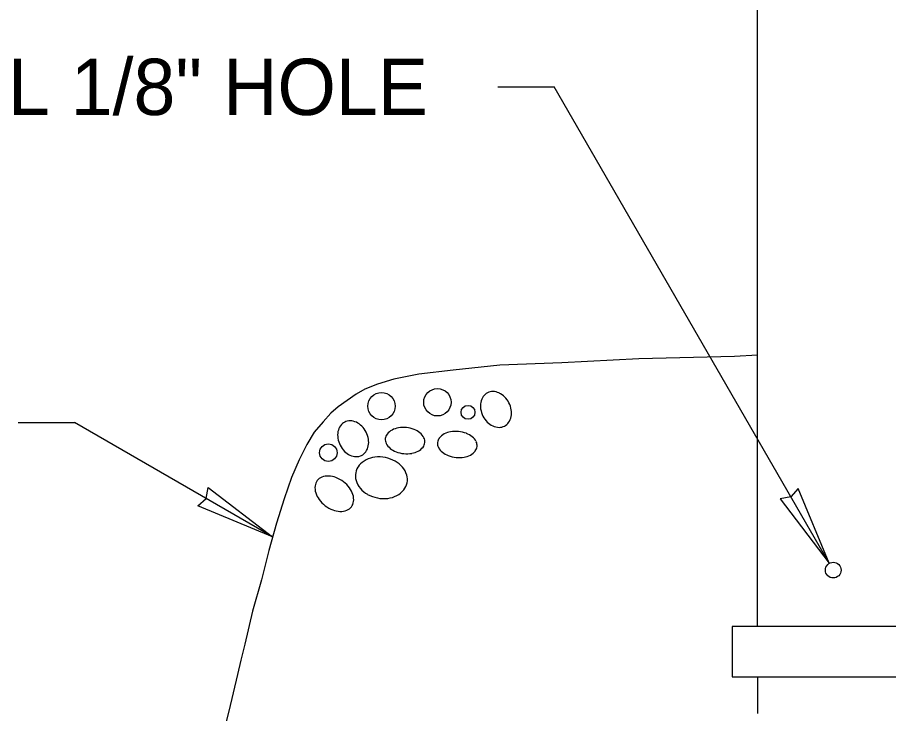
# Model space of a CAD drawing. Extents: x 99862 to 103151, y 99999 to 102075.
# Drawn here: x 100382.8 to 100630.4, y 100412.2 to 100610.1 of the extents above; entities that cross this region are included whole.
import ezdxf

# ---------------------------------------------------------------- set-up
doc = ezdxf.new("R2010")
doc.units = 0
for name, color, linetype in [('Level 10', 7, 'Continuous'), ('Level 11', 7, 'Continuous'), ('Level 15', 7, 'Continuous'), ('Level 20', 7, 'Continuous'), ('Level 6', 7, 'Continuous'), ('Level 7', 7, 'Continuous')]:
    doc.layers.add(name, color=color, linetype=linetype)

msp = doc.modelspace()

# ---------------------------------------------------------------- linework, layer by layer
at = {"layer": 'Level 10'}
for centre, radius in [((100486.3, 100499.58), 3.89), ((100502.16, 100500.67), 3.89), ((100510.87, 100497.82), 1.97), ((100471.17, 100486.35), 2.5)]:
    msp.add_circle(centre, radius, dxfattribs=at)
for centre, radius, start, end in [((100518.8, 100499.82), 4.38, 144.8875, 168.9625), ((100517.88, 100500.46), 3.26, 116.9203, 144.8875), ((100517.88, 100500.46), 3.26, 88.9532, 116.9203), ((100517.86, 100499.35), 4.38, 64.8782, 88.9532), ((100517.42, 100498.4), 5.42, 44.8275, 64.8782), ((100516.45, 100497.44), 6.79, 26.9203, 44.8275), ((100519.82, 100499.62), 5.42, 168.9625, 189.0132), ((100516.45, 100497.44), 6.79, 9.0132, 26.9203), ((100521.17, 100499.83), 6.79, 189.0132, 206.9203), ((100517.8, 100497.65), 5.42, 348.9625, 9.0132), ((100477.3, 100492.14), 3.26, 116.9203, 144.8875), ((100477.3, 100492.14), 3.26, 88.9532, 116.9203), ((100477.28, 100491.02), 4.38, 64.8782, 88.9532), ((100476.84, 100490.07), 5.42, 44.8275, 64.8782), ((100521.17, 100499.83), 6.79, 206.9203, 224.8275), ((100520.2, 100498.87), 5.42, 224.8275, 244.8782), ((100519.74, 100496.81), 3.26, 296.9203, 324.8875), ((100518.82, 100497.45), 4.38, 324.8875, 348.9625), ((100479.24, 100491.29), 5.42, 168.9625, 189.0132), ((100478.22, 100491.49), 4.38, 144.8875, 168.9625), ((100475.87, 100489.11), 6.79, 26.9203, 44.8275), ((100491.26, 100489), 4.28, 117.677, 142.1417), ((100492.1, 100487.4), 6.08, 99.5822, 117.677), ((100492.51, 100484.97), 8.55, 84.3418, 99.5822), ((100492.51, 100484.97), 8.55, 69.1013, 84.3418), ((100493.39, 100487.27), 6.08, 51.0065, 69.1013), ((100506.94, 100486.29), 6.08, 99.5822, 117.677), ((100507.35, 100483.86), 8.55, 84.3418, 99.5822), ((100507.35, 100483.86), 8.55, 69.1013, 84.3418), ((100519.76, 100497.93), 4.38, 244.8782, 268.9532), ((100519.74, 100496.81), 3.26, 268.9532, 296.9203), ((100480.59, 100491.51), 6.79, 189.0132, 206.9203), ((100475.87, 100489.11), 6.79, 9.0132, 26.9203), ((100477.22, 100489.33), 5.42, 348.9625, 9.0132), ((100489.85, 100490.09), 2.5, 174.3418, 206.5418), ((100489.85, 100490.09), 2.5, 142.1417, 174.3418), ((100494.52, 100488.67), 4.28, 26.5418, 51.0065), ((100496.12, 100489.47), 2.5, 354.3418, 26.5418), ((100504.7, 100488.98), 2.5, 142.1417, 174.3418), ((100506.1, 100487.89), 4.28, 117.677, 142.1417), ((100508.23, 100486.16), 6.08, 51.0065, 69.1013), ((100509.37, 100487.57), 4.28, 26.5418, 51.0065), ((100480.59, 100491.51), 6.79, 206.9203, 224.8275), ((100478.24, 100489.13), 4.38, 324.8875, 348.9625), ((100491.45, 100490.89), 4.28, 206.5418, 231.0065), ((100492.58, 100492.29), 6.08, 231.0065, 249.1013), ((100494.71, 100490.56), 4.28, 297.677, 322.1417), ((100496.12, 100489.47), 2.5, 322.1417, 354.3418), ((100504.7, 100488.98), 2.5, 174.3418, 206.5418), ((100506.29, 100489.78), 4.28, 206.5418, 231.0065), ((100510.96, 100488.36), 2.5, 322.1417, 354.3418), ((100510.96, 100488.36), 2.5, 354.3418, 26.5418), ((100479.62, 100490.55), 5.42, 224.8275, 244.8782), ((100479.18, 100489.6), 4.38, 244.8782, 268.9532), ((100479.16, 100488.48), 3.26, 268.9532, 296.9203), ((100479.16, 100488.48), 3.26, 296.9203, 324.8875), ((100485.33, 100477.52), 7.6, 96.821, 116.938), ((100485.55, 100475.67), 9.46, 78.8127, 96.821), ((100485.55, 100475.67), 9.46, 60.8043, 78.8127), ((100493.46, 100494.59), 8.55, 249.1013, 264.3417), ((100493.46, 100494.59), 8.55, 264.3417, 279.5822), ((100493.87, 100492.16), 6.08, 279.5822, 297.677), ((100507.42, 100491.18), 6.08, 231.0065, 249.1013), ((100508.31, 100493.49), 8.55, 249.1013, 264.3417), ((100508.31, 100493.49), 8.55, 264.3417, 279.5822), ((100508.72, 100491.05), 6.08, 279.5822, 297.677), ((100509.55, 100489.45), 4.28, 297.677, 322.1417), ((100483.49, 100479.76), 4.63, 140.9882, 168.8127), ((100484.68, 100478.79), 6.17, 116.938, 140.9882), ((100486.46, 100477.29), 7.6, 40.6874, 60.8043), ((100483.49, 100479.76), 4.63, 168.8127, 196.6371), ((100487.55, 100478.23), 6.17, 16.6371, 40.6874), ((100489.02, 100478.67), 4.63, 348.8127, 16.6371), ((100470.43, 100476.55), 3.04, 142.6002, 173.2747), ((100470.43, 100476.55), 3.04, 111.9256, 142.6002), ((100471.07, 100474.95), 4.76, 87.5276, 111.9256), ((100471, 100473.26), 6.45, 68.7329, 87.5276), ((100470.17, 100471.13), 8.74, 52.6002, 68.7329), ((100470.17, 100471.13), 8.74, 36.4674, 52.6002), ((100484.96, 100480.2), 6.17, 196.6371, 220.6874), ((100489.02, 100478.67), 4.63, 320.9882, 348.8127), ((100472.14, 100476.35), 4.76, 173.2747, 197.6727), ((100472.01, 100472.49), 6.45, 17.6727, 36.4674), ((100486.04, 100481.14), 7.6, 220.6874, 240.8043), ((100487.82, 100479.64), 6.17, 296.938, 320.9882), ((100473.75, 100476.86), 6.45, 197.6727, 216.4674), ((100475.59, 100478.22), 8.74, 216.4674, 232.6002), ((100475.33, 100472.8), 3.04, 322.6002, 353.2747), ((100473.62, 100473), 4.76, 353.2747, 17.6727), ((100486.95, 100482.76), 9.46, 240.8043, 258.8127), ((100486.95, 100482.76), 9.46, 258.8127, 276.821), ((100487.17, 100480.91), 7.6, 276.821, 296.938), ((100475.59, 100478.22), 8.74, 232.6002, 248.7329), ((100474.76, 100476.09), 6.45, 248.7329, 267.5276), ((100474.69, 100474.4), 4.76, 267.5276, 291.9256), ((100475.33, 100472.8), 3.04, 291.9256, 322.6002)]:
    msp.add_arc(centre, radius, start, end, dxfattribs=at)
at = {"layer": 'Level 11'}
msp.add_circle((100614.67, 100452.96), 2.24, dxfattribs=at)
at = {"layer": 'Level 15'}
for p, q in [((100519.34, 100590.35), (100535.34, 100590.35)), ((100613.55, 100454.9), (100535.34, 100590.35)), ((100383.05, 100494.93), (100399.05, 100494.93)), ((100455.34, 100462.42), (100399.05, 100494.93))]:
    msp.add_line(p, q, dxfattribs=at)
for points in [[(100455.34, 100462.42), (100434.08, 100471.25), (100436.48, 100473.31), (100437.06, 100476.42)], [(100613.55, 100454.9), (100604.72, 100476.16), (100602.66, 100473.76), (100599.55, 100473.18)]]:
    msp.add_lwpolyline(points, close=True, dxfattribs=at)
at = {"layer": 'Level 6'}
for p, q in [((100593.13, 100436.94), (100593.13, 100828.69)), ((100593.13, 100422.61), (100593.13, 100412.21))]:
    msp.add_line(p, q, dxfattribs=at)
msp.add_lwpolyline([(100585.93, 100422.61), (100643.34, 100422.61), (100643.34, 100436.94), (100585.93, 100436.94)], close=True, dxfattribs=at)
at = {"layer": 'Level 7'}
msp.add_lwpolyline([(100593.13, 100514.09), (100586.63, 100513.71), (100559.38, 100513.05), (100537.51, 100511.91), (100519.93, 100511.19), (100506.64, 100509.79), (100496.94, 100508.71), (100489.78, 100507.26), (100485.14, 100505.81), (100481.56, 100504.42), (100479.04, 100502.97), (100476.51, 100501.17), (100474.01, 100499.37), (100471.88, 100497.6), (100469.69, 100495.07), (100467.16, 100492.2), (100465.05, 100488.64), (100462.9, 100484.34), (100460.75, 100479.32), (100458.58, 100473.19), (100456.43, 100466.34), (100454.25, 100458.51), (100452.14, 100450.2), (100449.64, 100441.26), (100447.49, 100431.89), (100446.31, 100427.4), (100445.35, 100423.29), (100442.86, 100412.86), (100441.23, 100406.13)], dxfattribs=at)

# ---------------------------------------------------------------- texts
at = {"layer": 'Level 20'}
msp.add_text('DRILL 1/8" HOLE', height=16, dxfattribs=at).set_placement((100331.37, 100582.35))

doc.saveas('drawing.dxf')
